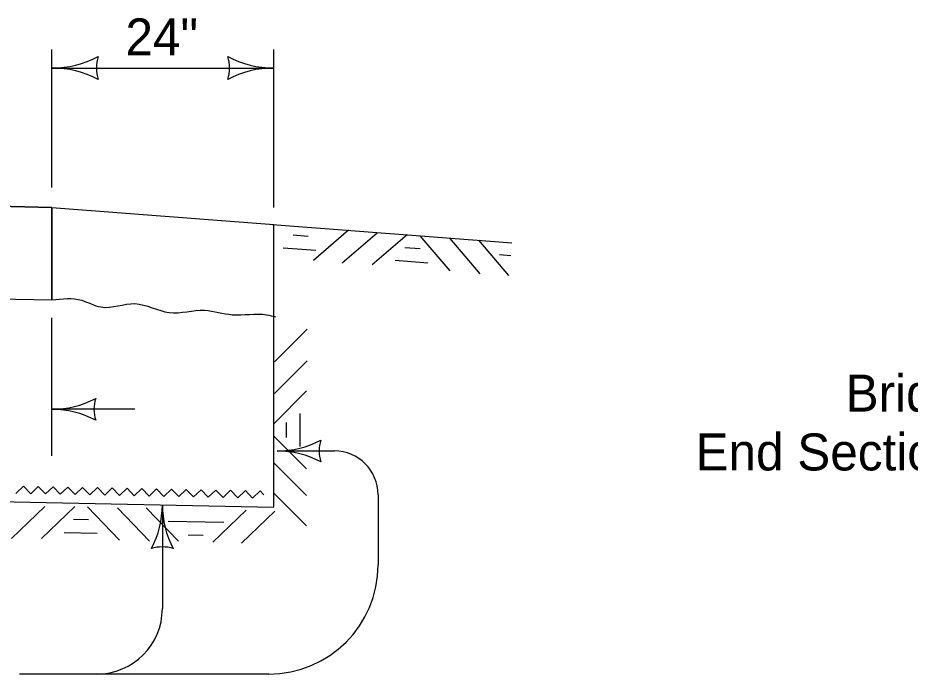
# Model space of a CAD drawing. Extents: x -2134934 to -2124557, y -2139046 to -2134021.
# Drawn here: x -2127032.7 to -2126646.7, y -2137912.4 to -2137628.5 of the extents above; entities that cross this region are included whole.
import ezdxf

# ---------------------------------------------------------------- set-up
doc = ezdxf.new("R2010")
doc.units = 0
doc.layers.add('BridgeSuperStructureExisting', color=7, linetype='Continuous')
doc.layers.add('dsnStdLabel', color=7, linetype='Continuous')

msp = doc.modelspace()

# ---------------------------------------------------------------- linework, layer by layer
at = {"layer": 'BridgeSuperStructureExisting'}
for p, q in [((-2127017.9, -2137701.9), (-2127017.9, -2137642.2)), ((-2126921.9, -2137710.47), (-2126921.9, -2137642.2)), ((-2127017.9, -2137650.18), (-2126921.9, -2137650.18)), ((-2127017.9, -2137710.47), (-2127390.83, -2137702.98)), ((-2127390.83, -2137702.98), (-2127017.9, -2137710.47)), ((-2127017.9, -2137750.47), (-2127017.9, -2137710.47)), ((-2127017.9, -2137710.47), (-2127017.9, -2137750.47)), ((-2127017.9, -2137710.47), (-2126921.9, -2137717.85)), ((-2126922.54, -2137717.86), (-2126819.08, -2137725.82)), ((-2126921.9, -2137840.12), (-2126921.9, -2137717.91)), ((-2126889.63, -2137720.39), (-2126904.82, -2137733.4)), ((-2126877.24, -2137721.57), (-2126892.42, -2137734.58)), ((-2126864.25, -2137722.34), (-2126879.44, -2137735.36)), ((-2126858.85, -2137722.76), (-2126845.84, -2137737.94)), ((-2126845.9, -2137723.98), (-2126832.89, -2137739.17)), ((-2126833.47, -2137724.71), (-2126820.46, -2137739.9)), ((-2127390.83, -2137742.99), (-2127017.9, -2137750.47)), ((-2127390.83, -2137742.99), (-2127017.9, -2137750.47)), ((-2127017.9, -2137818.01), (-2127017.9, -2137758.31)), ((-2126921.68, -2137777.23), (-2126907.53, -2137763.09)), ((-2126921.68, -2137791.03), (-2126907.53, -2137776.89)), ((-2126921.9, -2137804.04), (-2126907.76, -2137789.9)), ((-2126982.12, -2137797.83), (-2127017.9, -2137797.83)), ((-2126921.9, -2137809.45), (-2126907.76, -2137823.59)), ((-2126895.77, -2137815.86), (-2126920.49, -2137815.86)), ((-2126921.9, -2137821.03), (-2126907.76, -2137835.17)), ((-2127390.83, -2137830.73), (-2126921.91, -2137840.14)), ((-2126921.9, -2137834.09), (-2126907.76, -2137848.23)), ((-2126876.86, -2137834.77), (-2126876.86, -2137865.12)), ((-2127020.98, -2137839.86), (-2127035.41, -2137853.71)), ((-2127007.97, -2137839.89), (-2127022.4, -2137853.75)), ((-2127002.56, -2137840), (-2126988.71, -2137854.42)), ((-2126970.17, -2137839.17), (-2126970.17, -2137884.03)), ((-2126989.56, -2137840.49), (-2126975.71, -2137854.91)), ((-2126977.11, -2137840.51), (-2126963.25, -2137854.93)), ((-2126933.89, -2137841.38), (-2126948.32, -2137855.23)), ((-2126921.45, -2137841.85), (-2126935.87, -2137855.71)), ((-2126924.13, -2137912.39), (-2127031.9, -2137912.39))]:
    msp.add_line(p, q, dxfattribs=at)
for points in [[(-2126913.62, -2137722.4), (-2126907.11, -2137722.9)], [(-2126917.89, -2137727.95), (-2126903.74, -2137729.03)], [(-2126865.23, -2137727.78), (-2126858.72, -2137728.28)], [(-2126824.34, -2137730.9), (-2126819.5, -2137731.28)], [(-2126869.5, -2137733.33), (-2126855.35, -2137734.41)], [(-2126910.55, -2137813.84), (-2126910.55, -2137799.65)], [(-2126916.4, -2137810.01), (-2126916.4, -2137803.48)], [(-2127033.49, -2137834.2), (-2127030.22, -2137831.06), (-2127027.09, -2137834.33), (-2127023.83, -2137831.19), (-2127020.69, -2137834.45), (-2127017.43, -2137831.32), (-2127014.29, -2137834.58), (-2127011.03, -2137831.45), (-2127007.89, -2137834.71), (-2127004.63, -2137831.58), (-2127003.06, -2137833.21)], [(-2127003.06, -2137833.21), (-2127001.49, -2137834.84), (-2126998.23, -2137831.7), (-2126995.1, -2137834.97), (-2126991.83, -2137831.83), (-2126988.7, -2137835.1), (-2126985.43, -2137831.96), (-2126982.3, -2137835.22), (-2126979.04, -2137832.09), (-2126975.9, -2137835.35), (-2126972.64, -2137832.22), (-2126969.5, -2137835.48), (-2126966.24, -2137832.35), (-2126963.1, -2137835.61), (-2126959.84, -2137832.47), (-2126956.7, -2137835.74), (-2126953.44, -2137832.6), (-2126950.31, -2137835.87), (-2126947.04, -2137832.73), (-2126943.91, -2137835.99), (-2126940.64, -2137832.86), (-2126937.51, -2137836.12), (-2126934.24, -2137832.99), (-2126931.11, -2137836.25), (-2126927.85, -2137833.12), (-2126926.28, -2137834.75)], [(-2127008.64, -2137845.38), (-2127002.11, -2137845.51)], [(-2126967.64, -2137846.18), (-2126943.58, -2137846.66)], [(-2127012.59, -2137851.15), (-2126998.4, -2137851.44)], [(-2126958.99, -2137852.15), (-2126952.46, -2137852.28)]]:
    msp.add_lwpolyline(points, dxfattribs=at)
for centre, radius, start, end in [((-2127017.9, -2137607.68), 42.5, 270, 298.0725), ((-2126982.27, -2137650.18), 16.42, 162.2666, 197.7334), ((-2126957.54, -2137650.18), 16.42, 342.2666, 17.7333), ((-2126921.9, -2137607.68), 42.5, 241.9275, 270), ((-2126957.54, -2137650.18), 16.42, 342.2666, 17.7333), ((-2126921.9, -2137607.68), 42.5, 241.9275, 270), ((-2127017.9, -2137692.68), 42.5, 61.9275, 90), ((-2126921.9, -2137692.68), 42.5, 90, 118.0725), ((-2126921.9, -2137692.68), 42.5, 90, 118.0725), ((-2127017.9, -2137757.66), 40.18, 270, 298.0725), ((-2126984.22, -2137797.83), 15.52, 162.2666, 197.7334), ((-2127017.9, -2137838.01), 40.18, 61.9275, 90), ((-2126920.49, -2137775.68), 40.18, 270, 298.0725), ((-2126920.49, -2137775.68), 40.18, 270, 298.0725), ((-2126886.8, -2137815.86), 15.52, 162.2666, 197.7334), ((-2126886.8, -2137815.86), 15.52, 162.2666, 197.7334), ((-2126920.49, -2137856.03), 40.18, 61.9275, 90), ((-2126920.49, -2137856.03), 40.18, 61.9275, 90), ((-2126895.77, -2137834.76), 18.91, 0, 90), ((-2127010.35, -2137839.17), 40.18, 331.9275, 360), ((-2126930, -2137839.17), 40.18, 180, 208.0725), ((-2126970.17, -2137872.86), 15.52, 72.2666, 107.7334), ((-2126924.13, -2137865.13), 47.27, 270, 360), ((-2126998.53, -2137884.03), 28.36, 270, 360)]:
    msp.add_arc(centre, radius, start, end, dxfattribs=at)
msp.add_spline([(-2127017.9, -2137750.47), (-2127004.95, -2137750.68), (-2126996.82, -2137753.55), (-2126982, -2137752.12), (-2126967.17, -2137755.94), (-2126951.87, -2137754.99), (-2126939.91, -2137756.9), (-2126925.09, -2137756.9), (-2126921.26, -2137757.86)], degree=3, dxfattribs=at)

# ---------------------------------------------------------------- texts
for s, p in [('Bridge Rail', (-2126674.65, -2137798.82)), ('End Section (typ.)', (-2126739.58, -2137824.27))]:
    msp.add_text(s, height=16, dxfattribs=at).set_placement(p)
at = {"layer": 'dsnStdLabel'}
msp.add_text('24"', height=16, dxfattribs=at).set_placement((-2126986.12, -2137644.72))

doc.saveas('drawing.dxf')
